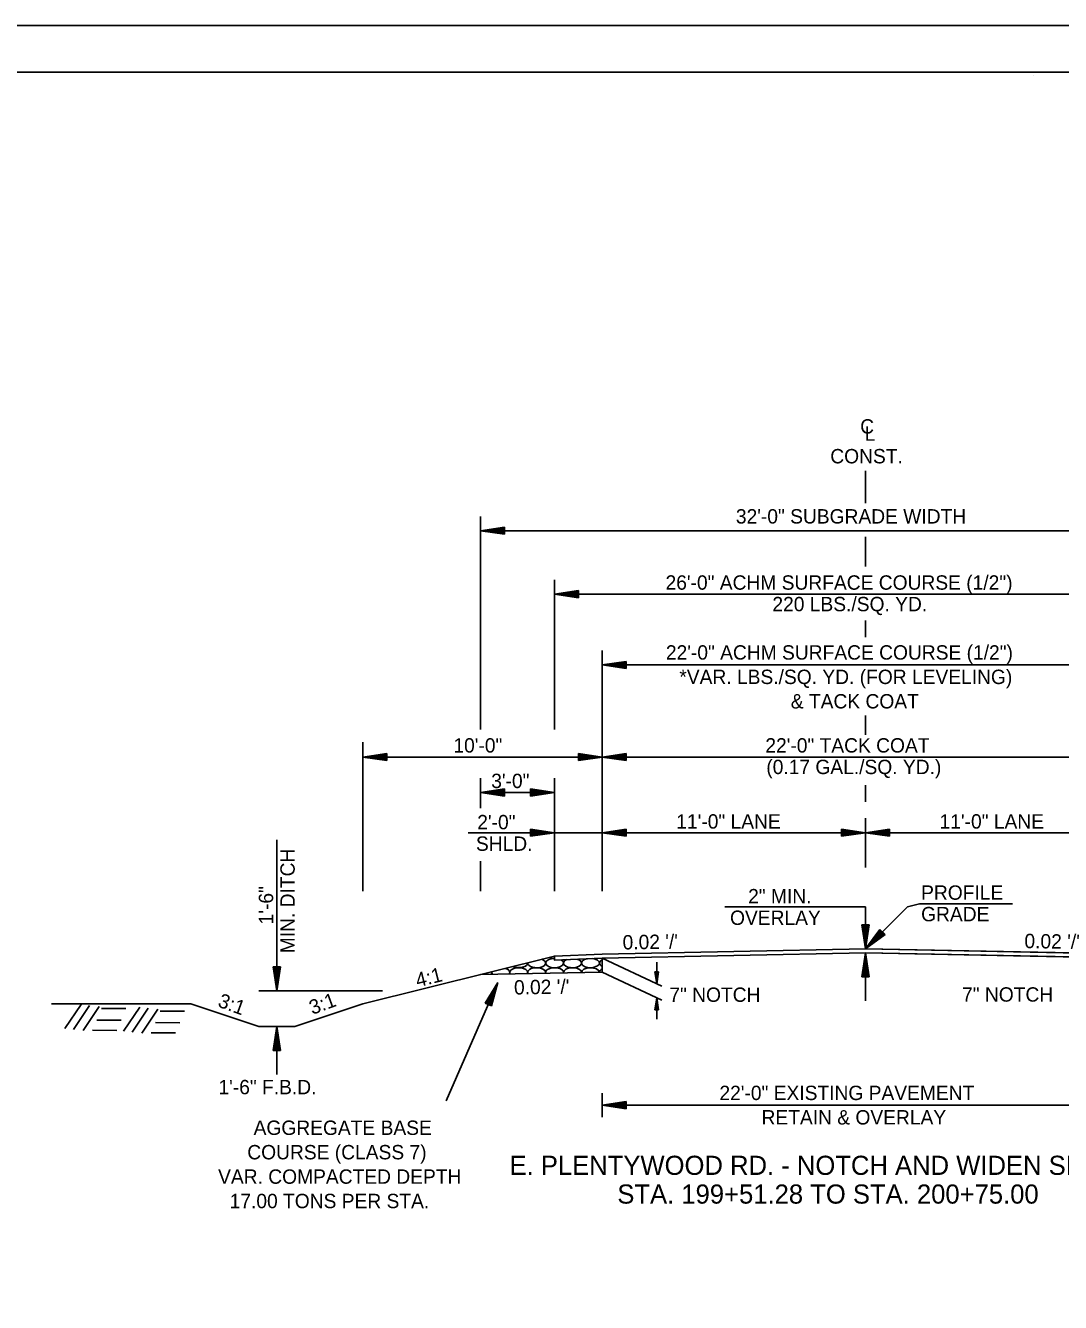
# Model space of a CAD drawing. Extents: x 1371763 to 1372860, y 385599 to 385872.
# Drawn here: x 1372733.4 to 1372776.6, y 385651.9 to 385705.3 of the extents above; entities that cross this region are included whole.
import ezdxf

# ---------------------------------------------------------------- set-up
doc = ezdxf.new("R2010")
doc.units = 0
for name, color, linetype in [('R_Border', 7, 'Continuous'), ('R_Draft', 7, 'Continuous'), ('R_Fin Surface', 7, 'Continuous'), ('R_No Plot', 7, 'Continuous')]:
    doc.layers.add(name, color=color, linetype=linetype)

msp = doc.modelspace()

# ---------------------------------------------------------------- linework, layer by layer
at = {"layer": 'R_Border'}
for p, q in [((1372699.208, 385703.307), (1372857.298, 385703.307)), ((1372775.468, 385703.177), (1372775.468, 385703.177)), ((1372775.468, 385703.177), (1372775.468, 385703.177))]:
    msp.add_line(p, q, dxfattribs=at)
at = {"layer": 'R_Draft'}
for p, q in [((1372768.462, 385685.304), (1372768.462, 385686.654)), ((1372752.376, 385675.852), (1372752.376, 385684.754)), ((1372753.376, 385684.304), (1372752.376, 385684.154)), ((1372752.376, 385684.154), (1372784.547, 385684.154)), ((1372753.376, 385684.004), (1372752.376, 385684.154)), ((1372753.376, 385684.279), (1372752.543, 385684.154)), ((1372753.376, 385684.029), (1372752.543, 385684.154)), ((1372753.376, 385684.254), (1372752.715, 385684.154)), ((1372753.376, 385684.055), (1372752.715, 385684.154)), ((1372753.376, 385684.229), (1372752.882, 385684.154)), ((1372753.376, 385684.08), (1372752.882, 385684.154)), ((1372753.376, 385684.203), (1372753.051, 385684.154)), ((1372753.376, 385684.105), (1372753.051, 385684.154)), ((1372753.376, 385684.178), (1372753.218, 385684.154)), ((1372753.376, 385684.131), (1372753.218, 385684.154)), ((1372753.376, 385684.304), (1372753.376, 385684.004)), ((1372768.462, 385682.654), (1372768.462, 385683.904)), ((1372755.463, 385675.852), (1372755.463, 385682.102)), ((1372756.463, 385681.652), (1372755.463, 385681.502)), ((1372756.463, 385681.352), (1372755.463, 385681.502)), ((1372755.463, 385681.502), (1372781.46, 385681.502)), ((1372756.463, 385681.627), (1372755.63, 385681.502)), ((1372756.463, 385681.377), (1372755.63, 385681.502)), ((1372756.463, 385681.602), (1372755.802, 385681.502)), ((1372756.463, 385681.403), (1372755.802, 385681.502)), ((1372756.463, 385681.577), (1372755.969, 385681.502)), ((1372756.463, 385681.428), (1372755.969, 385681.502)), ((1372756.463, 385681.551), (1372756.138, 385681.502)), ((1372756.463, 385681.453), (1372756.138, 385681.502)), ((1372756.463, 385681.526), (1372756.305, 385681.502)), ((1372756.463, 385681.479), (1372756.305, 385681.502)), ((1372756.463, 385681.652), (1372756.463, 385681.352)), ((1372768.458, 385679.709), (1372768.458, 385680.41)), ((1372757.462, 385669.102), (1372757.462, 385679.146)), ((1372758.462, 385678.696), (1372757.462, 385678.546)), ((1372758.462, 385678.671), (1372757.629, 385678.546)), ((1372758.462, 385678.396), (1372758.462, 385678.696)), ((1372757.462, 385678.546), (1372779.462, 385678.547)), ((1372758.462, 385678.396), (1372757.462, 385678.546)), ((1372758.462, 385678.421), (1372757.629, 385678.546)), ((1372758.462, 385678.646), (1372757.801, 385678.546)), ((1372758.462, 385678.447), (1372757.801, 385678.546)), ((1372758.462, 385678.621), (1372757.967, 385678.546)), ((1372758.462, 385678.472), (1372757.967, 385678.546)), ((1372758.462, 385678.595), (1372758.137, 385678.546)), ((1372758.462, 385678.498), (1372758.137, 385678.546)), ((1372758.462, 385678.57), (1372758.304, 385678.546)), ((1372758.462, 385678.523), (1372758.304, 385678.546)), ((1372768.458, 385675.622), (1372768.458, 385676.432)), ((1372747.462, 385669.102), (1372747.462, 385675.327)), ((1372748.462, 385674.852), (1372747.462, 385674.702)), ((1372748.462, 385674.552), (1372747.462, 385674.702)), ((1372747.462, 385674.702), (1372757.462, 385674.702)), ((1372748.462, 385674.827), (1372747.629, 385674.702)), ((1372748.462, 385674.577), (1372747.629, 385674.702)), ((1372748.462, 385674.802), (1372747.801, 385674.702)), ((1372748.462, 385674.603), (1372747.801, 385674.702)), ((1372748.462, 385674.777), (1372747.967, 385674.702)), ((1372748.462, 385674.628), (1372747.967, 385674.702)), ((1372748.462, 385674.751), (1372748.137, 385674.702)), ((1372748.462, 385674.654), (1372748.137, 385674.702)), ((1372748.462, 385674.726), (1372748.304, 385674.702)), ((1372748.462, 385674.679), (1372748.304, 385674.702)), ((1372748.462, 385674.552), (1372748.462, 385674.852)), ((1372756.462, 385674.852), (1372757.462, 385674.702)), ((1372756.462, 385674.552), (1372756.462, 385674.852)), ((1372756.462, 385674.827), (1372757.295, 385674.702)), ((1372756.462, 385674.802), (1372757.123, 385674.702)), ((1372756.462, 385674.777), (1372756.956, 385674.702)), ((1372756.462, 385674.751), (1372756.787, 385674.702)), ((1372756.462, 385674.726), (1372756.62, 385674.702)), ((1372756.462, 385674.552), (1372757.462, 385674.702)), ((1372756.462, 385674.654), (1372756.787, 385674.702)), ((1372756.462, 385674.603), (1372757.123, 385674.702)), ((1372756.462, 385674.577), (1372757.295, 385674.702)), ((1372756.462, 385674.628), (1372756.956, 385674.702)), ((1372756.462, 385674.679), (1372756.62, 385674.702)), ((1372758.462, 385674.852), (1372757.462, 385674.702)), ((1372758.462, 385674.552), (1372757.462, 385674.702)), ((1372757.462, 385674.702), (1372779.462, 385674.702)), ((1372758.462, 385674.827), (1372757.629, 385674.702)), ((1372758.462, 385674.577), (1372757.629, 385674.702)), ((1372758.462, 385674.802), (1372757.801, 385674.702)), ((1372758.462, 385674.603), (1372757.801, 385674.702)), ((1372758.462, 385674.777), (1372757.967, 385674.702)), ((1372758.462, 385674.628), (1372757.967, 385674.702)), ((1372758.462, 385674.751), (1372758.137, 385674.702)), ((1372758.462, 385674.654), (1372758.137, 385674.702)), ((1372758.462, 385674.726), (1372758.304, 385674.702)), ((1372758.462, 385674.679), (1372758.304, 385674.702)), ((1372758.462, 385674.552), (1372758.462, 385674.852)), ((1372752.376, 385672.568), (1372752.376, 385673.818)), ((1372753.376, 385673.368), (1372752.376, 385673.218)), ((1372753.376, 385673.343), (1372752.543, 385673.218)), ((1372753.376, 385673.318), (1372752.715, 385673.218)), ((1372753.376, 385673.068), (1372753.376, 385673.368)), ((1372754.463, 385673.368), (1372755.463, 385673.218)), ((1372754.463, 385673.068), (1372754.463, 385673.368)), ((1372754.463, 385673.343), (1372755.296, 385673.218)), ((1372754.463, 385673.318), (1372755.124, 385673.218)), ((1372755.463, 385669.102), (1372755.463, 385673.818)), ((1372768.458, 385672.835), (1372768.458, 385673.521)), ((1372753.376, 385673.068), (1372752.376, 385673.218)), ((1372752.376, 385673.218), (1372755.463, 385673.218)), ((1372753.376, 385673.093), (1372752.543, 385673.218)), ((1372753.376, 385673.119), (1372752.715, 385673.218)), ((1372753.376, 385673.293), (1372752.882, 385673.218)), ((1372753.376, 385673.144), (1372752.882, 385673.218)), ((1372753.376, 385673.267), (1372753.051, 385673.218)), ((1372753.376, 385673.17), (1372753.051, 385673.218)), ((1372753.376, 385673.242), (1372753.218, 385673.218)), ((1372753.376, 385673.195), (1372753.218, 385673.218)), ((1372754.463, 385673.293), (1372754.958, 385673.218)), ((1372754.463, 385673.267), (1372754.788, 385673.218)), ((1372754.463, 385673.242), (1372754.621, 385673.218)), ((1372754.463, 385673.068), (1372755.463, 385673.218)), ((1372754.463, 385673.17), (1372754.788, 385673.218)), ((1372754.463, 385673.119), (1372755.124, 385673.218)), ((1372754.463, 385673.093), (1372755.296, 385673.218)), ((1372754.463, 385673.144), (1372754.958, 385673.218)), ((1372754.463, 385673.195), (1372754.621, 385673.218)), ((1372768.458, 385670.087), (1372768.458, 385672.141)), ((1372743.867, 385664.942), (1372743.867, 385671.24)), ((1372751.858, 385671.541), (1372768.458, 385671.541)), ((1372754.463, 385671.691), (1372755.463, 385671.541)), ((1372754.463, 385671.391), (1372754.463, 385671.691)), ((1372754.463, 385671.666), (1372755.296, 385671.541)), ((1372754.463, 385671.64), (1372755.124, 385671.541)), ((1372754.463, 385671.615), (1372754.958, 385671.541)), ((1372754.463, 385671.59), (1372754.788, 385671.541)), ((1372754.463, 385671.564), (1372754.621, 385671.541)), ((1372754.463, 385671.391), (1372755.463, 385671.541)), ((1372754.463, 385671.492), (1372754.788, 385671.541)), ((1372754.463, 385671.441), (1372755.124, 385671.541)), ((1372754.463, 385671.416), (1372755.296, 385671.541)), ((1372754.463, 385671.466), (1372754.958, 385671.541)), ((1372754.463, 385671.517), (1372754.621, 385671.541)), ((1372758.458, 385671.691), (1372757.458, 385671.541)), ((1372758.458, 385671.391), (1372757.458, 385671.541)), ((1372758.458, 385671.666), (1372757.625, 385671.541)), ((1372758.458, 385671.416), (1372757.625, 385671.541)), ((1372758.458, 385671.64), (1372757.797, 385671.541)), ((1372758.458, 385671.441), (1372757.797, 385671.541)), ((1372758.458, 385671.615), (1372757.964, 385671.541)), ((1372758.458, 385671.466), (1372757.964, 385671.541)), ((1372758.458, 385671.59), (1372758.133, 385671.541)), ((1372758.458, 385671.492), (1372758.133, 385671.541)), ((1372758.458, 385671.564), (1372758.3, 385671.541)), ((1372758.458, 385671.517), (1372758.3, 385671.541)), ((1372758.458, 385671.391), (1372758.458, 385671.691)), ((1372767.458, 385671.691), (1372768.458, 385671.541)), ((1372767.458, 385671.391), (1372767.458, 385671.691)), ((1372767.458, 385671.666), (1372768.291, 385671.541)), ((1372767.458, 385671.64), (1372768.119, 385671.541)), ((1372767.458, 385671.615), (1372767.953, 385671.541)), ((1372767.458, 385671.59), (1372767.783, 385671.541)), ((1372767.458, 385671.564), (1372767.616, 385671.541)), ((1372767.458, 385671.391), (1372768.458, 385671.541)), ((1372767.458, 385671.492), (1372767.783, 385671.541)), ((1372767.458, 385671.441), (1372768.119, 385671.541)), ((1372767.458, 385671.416), (1372768.291, 385671.541)), ((1372767.458, 385671.466), (1372767.953, 385671.541)), ((1372767.458, 385671.517), (1372767.616, 385671.541)), ((1372769.458, 385671.691), (1372768.458, 385671.541)), ((1372769.458, 385671.391), (1372768.458, 385671.541)), ((1372768.458, 385671.541), (1372785.058, 385671.541)), ((1372769.458, 385671.666), (1372768.625, 385671.541)), ((1372769.458, 385671.416), (1372768.625, 385671.541)), ((1372769.458, 385671.64), (1372768.797, 385671.541)), ((1372769.458, 385671.441), (1372768.797, 385671.541)), ((1372769.458, 385671.615), (1372768.964, 385671.541)), ((1372769.458, 385671.466), (1372768.964, 385671.541)), ((1372769.458, 385671.59), (1372769.133, 385671.541)), ((1372769.458, 385671.492), (1372769.133, 385671.541)), ((1372769.458, 385671.564), (1372769.3, 385671.541)), ((1372769.458, 385671.517), (1372769.3, 385671.541)), ((1372769.458, 385671.391), (1372769.458, 385671.691)), ((1372752.376, 385669.102), (1372752.376, 385670.352)), ((1372770.212, 385668.439), (1372770.712, 385668.564)), ((1372770.712, 385668.564), (1372774.597, 385668.564)), ((1372768.462, 385668.439), (1372762.586, 385668.439)), ((1372768.462, 385666.689), (1372770.212, 385668.439)), ((1372768.462, 385666.689), (1372768.462, 385668.439)), ((1372768.312, 385667.689), (1372768.462, 385666.689)), ((1372768.312, 385667.689), (1372768.612, 385667.689)), ((1372768.337, 385667.689), (1372768.462, 385666.856)), ((1372768.362, 385667.689), (1372768.462, 385667.028)), ((1372768.387, 385667.689), (1372768.462, 385667.195)), ((1372768.413, 385667.689), (1372768.462, 385667.364)), ((1372768.438, 385667.689), (1372768.462, 385667.531)), ((1372768.612, 385667.689), (1372768.462, 385666.689)), ((1372768.511, 385667.689), (1372768.462, 385667.364)), ((1372768.561, 385667.689), (1372768.462, 385667.028)), ((1372768.587, 385667.689), (1372768.462, 385666.856)), ((1372768.536, 385667.689), (1372768.462, 385667.195)), ((1372768.485, 385667.689), (1372768.462, 385667.531)), ((1372769.063, 385667.503), (1372768.462, 385666.689)), ((1372769.081, 385667.485), (1372768.58, 385666.808)), ((1372769.099, 385667.467), (1372768.702, 385666.929)), ((1372769.116, 385667.449), (1372768.819, 385667.047)), ((1372769.275, 385667.29), (1372769.063, 385667.503)), ((1372769.275, 385667.29), (1372768.462, 385666.689)), ((1372769.257, 385667.308), (1372768.58, 385666.808)), ((1372769.239, 385667.326), (1372768.702, 385666.929)), ((1372769.222, 385667.344), (1372768.819, 385667.047)), ((1372769.134, 385667.431), (1372768.939, 385667.167)), ((1372769.203, 385667.362), (1372768.939, 385667.167)), ((1372769.152, 385667.413), (1372769.057, 385667.285)), ((1372769.186, 385667.38), (1372769.057, 385667.285)), ((1372755.463, 385666.39), (1372747.463, 385664.39)), ((1372757.462, 385666.469), (1372755.463, 385666.39)), ((1372755.463, 385666.39), (1372755.463, 385666.223)), ((1372768.462, 385666.689), (1372757.462, 385666.469)), ((1372768.462, 385666.689), (1372757.462, 385666.469)), ((1372768.462, 385666.523), (1372757.462, 385666.303)), ((1372757.462, 385666.303), (1372768.462, 385666.523)), ((1372768.312, 385665.523), (1372768.462, 385666.523)), ((1372768.462, 385666.689), (1372779.462, 385666.469)), ((1372779.462, 385666.469), (1372768.462, 385666.689)), ((1372768.462, 385666.523), (1372779.462, 385666.303)), ((1372768.612, 385665.523), (1372768.462, 385666.523)), ((1372768.462, 385666.523), (1372768.462, 385664.523)), ((1372743.717, 385665.942), (1372743.867, 385664.942)), ((1372744.017, 385665.942), (1372743.717, 385665.942)), ((1372743.742, 385665.942), (1372743.867, 385665.109)), ((1372743.768, 385665.942), (1372743.867, 385665.281)), ((1372743.793, 385665.942), (1372743.867, 385665.448)), ((1372743.818, 385665.942), (1372743.867, 385665.617)), ((1372743.844, 385665.942), (1372743.867, 385665.784)), ((1372744.017, 385665.942), (1372743.867, 385664.942)), ((1372743.916, 385665.942), (1372743.867, 385665.617)), ((1372743.967, 385665.942), (1372743.867, 385665.281)), ((1372743.992, 385665.942), (1372743.867, 385665.109)), ((1372743.942, 385665.942), (1372743.867, 385665.448)), ((1372743.891, 385665.942), (1372743.867, 385665.784)), ((1372755.463, 385666.223), (1372757.462, 385666.303)), ((1372757.462, 385666.303), (1372757.462, 385665.719)), ((1372757.462, 385666.303), (1372759.95, 385665.131)), ((1372759.737, 385665.231), (1372759.737, 385666.131)), ((1372768.337, 385665.523), (1372768.462, 385666.356)), ((1372768.362, 385665.523), (1372768.462, 385666.184)), ((1372768.387, 385665.523), (1372768.462, 385666.017)), ((1372768.413, 385665.523), (1372768.462, 385665.848)), ((1372768.587, 385665.523), (1372768.462, 385666.356)), ((1372768.561, 385665.523), (1372768.462, 385666.184)), ((1372768.536, 385665.523), (1372768.462, 385666.017)), ((1372768.51, 385665.523), (1372768.462, 385665.848)), ((1372757.462, 385665.719), (1372752.376, 385665.618)), ((1372757.462, 385665.719), (1372759.95, 385664.547)), ((1372759.662, 385665.731), (1372759.737, 385665.231)), ((1372759.662, 385665.731), (1372759.812, 385665.731)), ((1372759.674, 385665.731), (1372759.737, 385665.314)), ((1372759.687, 385665.731), (1372759.737, 385665.4)), ((1372759.7, 385665.731), (1372759.737, 385665.484)), ((1372759.713, 385665.731), (1372759.737, 385665.568)), ((1372759.725, 385665.731), (1372759.737, 385665.652)), ((1372759.812, 385665.731), (1372759.737, 385665.231)), ((1372759.761, 385665.731), (1372759.737, 385665.568)), ((1372759.787, 385665.731), (1372759.737, 385665.4)), ((1372759.799, 385665.731), (1372759.737, 385665.314)), ((1372759.774, 385665.731), (1372759.737, 385665.484)), ((1372759.749, 385665.731), (1372759.737, 385665.652)), ((1372768.612, 385665.523), (1372768.312, 385665.523)), ((1372768.438, 385665.523), (1372768.462, 385665.681)), ((1372768.485, 385665.523), (1372768.462, 385665.681)), ((1372743.117, 385664.942), (1372748.273, 385664.942)), ((1372753.104, 385665.28), (1372750.933, 385660.336)), ((1372752.564, 385664.425), (1372753.104, 385665.28)), ((1372752.587, 385664.415), (1372753.037, 385665.127)), ((1372752.611, 385664.405), (1372752.967, 385664.97)), ((1372752.634, 385664.395), (1372752.901, 385664.817)), ((1372752.77, 385664.335), (1372752.901, 385664.817)), ((1372752.793, 385664.325), (1372752.967, 385664.97)), ((1372752.816, 385664.314), (1372753.037, 385665.127)), ((1372752.839, 385664.304), (1372753.104, 385665.28)), ((1372735.007, 385663.358), (1372735.683, 385664.36)), ((1372735.366, 385663.317), (1372736.042, 385664.318)), ((1372735.766, 385663.275), (1372736.442, 385664.277)), ((1372737.46, 385663.25), (1372738.136, 385664.251)), ((1372752.839, 385664.304), (1372752.564, 385664.425)), ((1372752.657, 385664.384), (1372752.832, 385664.662)), ((1372752.68, 385664.374), (1372752.765, 385664.509)), ((1372752.723, 385664.355), (1372752.765, 385664.509)), ((1372752.746, 385664.345), (1372752.832, 385664.662)), ((1372759.662, 385664.148), (1372759.737, 385664.648)), ((1372759.674, 385664.148), (1372759.737, 385664.564)), ((1372759.687, 385664.148), (1372759.737, 385664.478)), ((1372759.7, 385664.148), (1372759.737, 385664.395)), ((1372759.712, 385664.148), (1372759.737, 385664.31)), ((1372759.812, 385664.148), (1372759.737, 385664.648)), ((1372759.737, 385663.748), (1372759.737, 385664.648)), ((1372759.799, 385664.148), (1372759.737, 385664.564)), ((1372759.787, 385664.148), (1372759.737, 385664.478)), ((1372759.774, 385664.148), (1372759.737, 385664.395)), ((1372759.761, 385664.148), (1372759.737, 385664.31)), ((1372736.342, 385663.717), (1372737.36, 385663.709)), ((1372736.542, 385664.201), (1372737.56, 385664.193)), ((1372737.819, 385663.208), (1372738.494, 385664.21)), ((1372738.219, 385663.167), (1372738.895, 385664.168)), ((1372738.995, 385664.093), (1372740.013, 385664.085)), ((1372759.812, 385664.148), (1372759.662, 385664.148)), ((1372759.725, 385664.148), (1372759.737, 385664.227)), ((1372759.749, 385664.148), (1372759.737, 385664.227)), ((1372736.167, 385663.292), (1372737.185, 385663.283)), ((1372738.619, 385663.183), (1372739.637, 385663.175)), ((1372738.795, 385663.609), (1372739.813, 385663.6)), ((1372744.617, 385663.441), (1372743.117, 385663.441)), ((1372743.717, 385662.441), (1372743.867, 385663.441)), ((1372743.742, 385662.441), (1372743.867, 385663.274)), ((1372744.017, 385662.441), (1372743.867, 385663.441)), ((1372743.867, 385661.441), (1372743.867, 385663.441)), ((1372743.992, 385662.441), (1372743.867, 385663.274)), ((1372743.768, 385662.441), (1372743.867, 385663.102)), ((1372743.793, 385662.441), (1372743.867, 385662.935)), ((1372743.819, 385662.441), (1372743.867, 385662.766)), ((1372743.967, 385662.441), (1372743.867, 385663.102)), ((1372743.942, 385662.441), (1372743.867, 385662.935)), ((1372743.916, 385662.441), (1372743.867, 385662.766)), ((1372743.717, 385662.441), (1372744.017, 385662.441)), ((1372743.844, 385662.441), (1372743.867, 385662.599)), ((1372743.891, 385662.441), (1372743.867, 385662.599)), ((1372757.462, 385659.663), (1372757.462, 385660.663)), ((1372758.462, 385660.313), (1372757.462, 385660.163)), ((1372758.462, 385660.013), (1372757.462, 385660.163)), ((1372757.462, 385660.163), (1372779.462, 385660.163)), ((1372758.462, 385660.288), (1372757.629, 385660.163)), ((1372758.462, 385660.038), (1372757.629, 385660.163)), ((1372758.462, 385660.263), (1372757.801, 385660.163)), ((1372758.462, 385660.064), (1372757.801, 385660.163)), ((1372758.462, 385660.238), (1372757.967, 385660.163)), ((1372758.462, 385660.089), (1372757.967, 385660.163)), ((1372758.462, 385660.212), (1372758.137, 385660.163)), ((1372758.462, 385660.114), (1372758.137, 385660.163)), ((1372758.462, 385660.187), (1372758.304, 385660.163)), ((1372758.462, 385660.14), (1372758.304, 385660.163)), ((1372758.462, 385660.313), (1372758.462, 385660.013))]:
    msp.add_line(p, q, dxfattribs=at)
for points in [[(1372752.376, 385665.618), (1372757.462, 385665.719), (1372757.462, 385666.303), (1372768.462, 385666.523), (1372779.462, 385666.303), (1372779.462, 385665.719), (1372784.547, 385665.618)], [(1372757.462, 385666.469), (1372755.463, 385666.39), (1372755.463, 385666.223)], [(1372768.462, 385666.523), (1372779.462, 385666.303), (1372781.46, 385666.223), (1372781.46, 385666.389)]]:
    msp.add_lwpolyline(points, dxfattribs=at)
msp.add_lwpolyline([(1372755.463, 385666.39), (1372757.462, 385666.469), (1372768.462, 385666.689), (1372779.462, 385666.469), (1372781.46, 385666.389), (1372781.46, 385666.223), (1372779.462, 385666.303), (1372768.462, 385666.523), (1372757.462, 385666.303), (1372755.463, 385666.223)], close=True, dxfattribs=at)
for centre, start_param, end_param in [((1372753.218, 385665.707), 0.733421, 1.044516), ((1372753.968, 385665.707), 6.020095, 9.765067), ((1372753.968, 385666.096), 3.971782, 6.352466), ((1372754.719, 385665.707), 6.100016, 9.685145), ((1372754.719, 385666.096), 3.069908, 6.553422), ((1372754.719, 385666.096), 0.270236, 0.971155), ((1372755.469, 385666.096), 1.585197, 7.071629), ((1372755.469, 385665.707), 1.585197, 3.323457), ((1372755.469, 385666.484), 4.039765, 4.697988), ((1372755.469, 385665.707), 6.178519, 7.868382), ((1372756.219, 385666.096), 2.279894, 7.298928), ((1372756.219, 385665.707), 6.256141, 9.529021), ((1372756.969, 385666.096), 1.92912, 7.649703), ((1372756.969, 385665.707), 0.050182, 3.168609), ((1372757.72, 385666.096), 2.328474, 3.954711), ((1372757.72, 385665.707), 2.328474, 3.091313), ((1372752.468, 385665.707), 5.853348, 6.292914), ((1372753.218, 385665.707), 2.996547, 3.563848), ((1372752.468, 385665.707), 0.009729, 0.135461), ((1372753.218, 385665.707), 5.938129, 7.016606)]:
    msp.add_ellipse(centre, major_axis=(0.375, 0), ratio=0.517889, start_param=start_param, end_param=end_param, dxfattribs=at)
at = {"layer": 'R_Fin Surface'}
for p, q in [((1372734.454, 385664.39), (1372740.271, 385664.39)), ((1372740.271, 385664.39), (1372743.117, 385663.441)), ((1372744.617, 385663.441), (1372747.463, 385664.39)), ((1372743.117, 385663.441), (1372744.617, 385663.441))]:
    msp.add_line(p, q, dxfattribs=at)
at = {"layer": 'R_No Plot'}
msp.add_line((1372693.007, 385705.254), (1372859.674, 385705.254), dxfattribs=at)
for points in [[(1372693.004, 385705.254), (1372859.674, 385705.254), (1372859.674, 385598.585), (1372693.004, 385598.585)], [(1372816.168, 385703.307), (1372825.978, 385703.307), (1372825.978, 385698.367), (1372834.034, 385698.367), (1372845.634, 385698.367), (1372845.634, 385682.032), (1372857.238, 385682.032), (1372857.298, 385600.577), (1372699.208, 385600.577), (1372699.208, 385703.307)]]:
    msp.add_lwpolyline(points, close=True, dxfattribs=at)

# ---------------------------------------------------------------- texts
at = {"layer": 'R_Draft'}
for s, rotation, p in [('C', 360, (1372768.237, 385688.211)), ('L', 360, (1372768.424, 385687.911)), ('CONST.', 360, (1372766.988, 385686.967)), ('32\'-0" SUBGRADE WIDTH', 360, (1372763.043, 385684.454)), ('26\'-0" ACHM SURFACE COURSE (1/2")', 360, (1372760.104, 385681.69)), ('220 LBS./SQ. YD.', 360, (1372764.569, 385680.79)), ('22\'-0" ACHM SURFACE COURSE (1/2")', 360, (1372760.119, 385678.77)), ('*VAR. LBS./SQ. YD. (FOR LEVELING)', 360, (1372760.681, 385677.75)), ('& TACK COAT', 360, (1372765.337, 385676.73)), ('10\'-0"', 360, (1372751.241, 385674.888)), ('22\'-0" TACK COAT', 360, (1372764.274, 385674.888)), ('(0.17 GAL./SQ. YD.)', 360, (1372764.314, 385673.988)), ('3\'-0"', 360, (1372752.821, 385673.405)), ('2\'-0"', 0, (1372752.237, 385671.683)), ('11\'-0" LANE', 360, (1372760.554, 385671.712)), ('11\'-0" LANE', 360, (1372771.554, 385671.712)), ('SHLD.', 0, (1372752.183, 385670.783)), ('MIN. DITCH', 90, (1372744.611, 385666.505)), ('1\'-6"', 90, (1372743.711, 385667.712)), ("0.02 '/'", 0.9853, (1372758.315, 385666.661)), ("0.02 '/'", 359.0147, (1372775.094, 385666.722)), ('4:1', 14.0362, (1372749.744, 385665.077)), ("0.02 '/'", 0.9853, (1372753.778, 385664.779)), ('3:1', 340.0022, (1372741.36, 385664.287)), ('3:1', 19.9978, (1372745.348, 385663.931)), ('1\'-6" F.B.D.', 360, (1372741.425, 385660.616)), ('22\'-0" EXISTING PAVEMENT', 360, (1372762.356, 385660.373)), ('AGGREGATE BASE ', 0, (1372742.894, 385658.917)), ('RETAIN & OVERLAY', 360, (1372764.115, 385659.353)), ('COURSE (CLASS 7)', 0, (1372742.63, 385657.897)), ('VAR. COMPACTED DEPTH', 0, (1372741.411, 385656.877)), ('17.00 TONS PER STA.', 0, (1372741.893, 385655.857))]:
    msp.add_text(s, height=0.6, rotation=rotation, dxfattribs=at).set_placement(p)
for s, height, p in [('2" MIN.', 0.6, (1372763.555, 385668.589)), ('PROFILE', 0.6, (1372770.782, 385668.74)), ('OVERLAY', 0.6, (1372762.799, 385667.689)), ('GRADE', 0.6, (1372770.782, 385667.84)), ('7" NOTCH', 0.6, (1372760.263, 385664.474)), ('7" NOTCH', 0.6, (1372772.494, 385664.484)), ('E. PLENTYWOOD RD. - NOTCH AND WIDEN SECTION', 0.8, (1372753.586, 385657.248)), ('STA. 199+51.28 TO STA. 200+75.00', 0.8, (1372758.09, 385656.048))]:
    msp.add_text(s, height=height, dxfattribs=at).set_placement(p)

doc.saveas('drawing.dxf')
